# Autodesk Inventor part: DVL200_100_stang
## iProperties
Created: 2009-09
Part Number: DVL200_100_stang
Document SubType Name: Modeling
Designer: TB
Mass: 4083 g
Surface Area: 1842.72 cm^2
Volume: 4083 cm^3
Density: 1 g/cm^3
Author: TB
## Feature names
1. Revolution1
2. Fillet1
3. Revolution2
